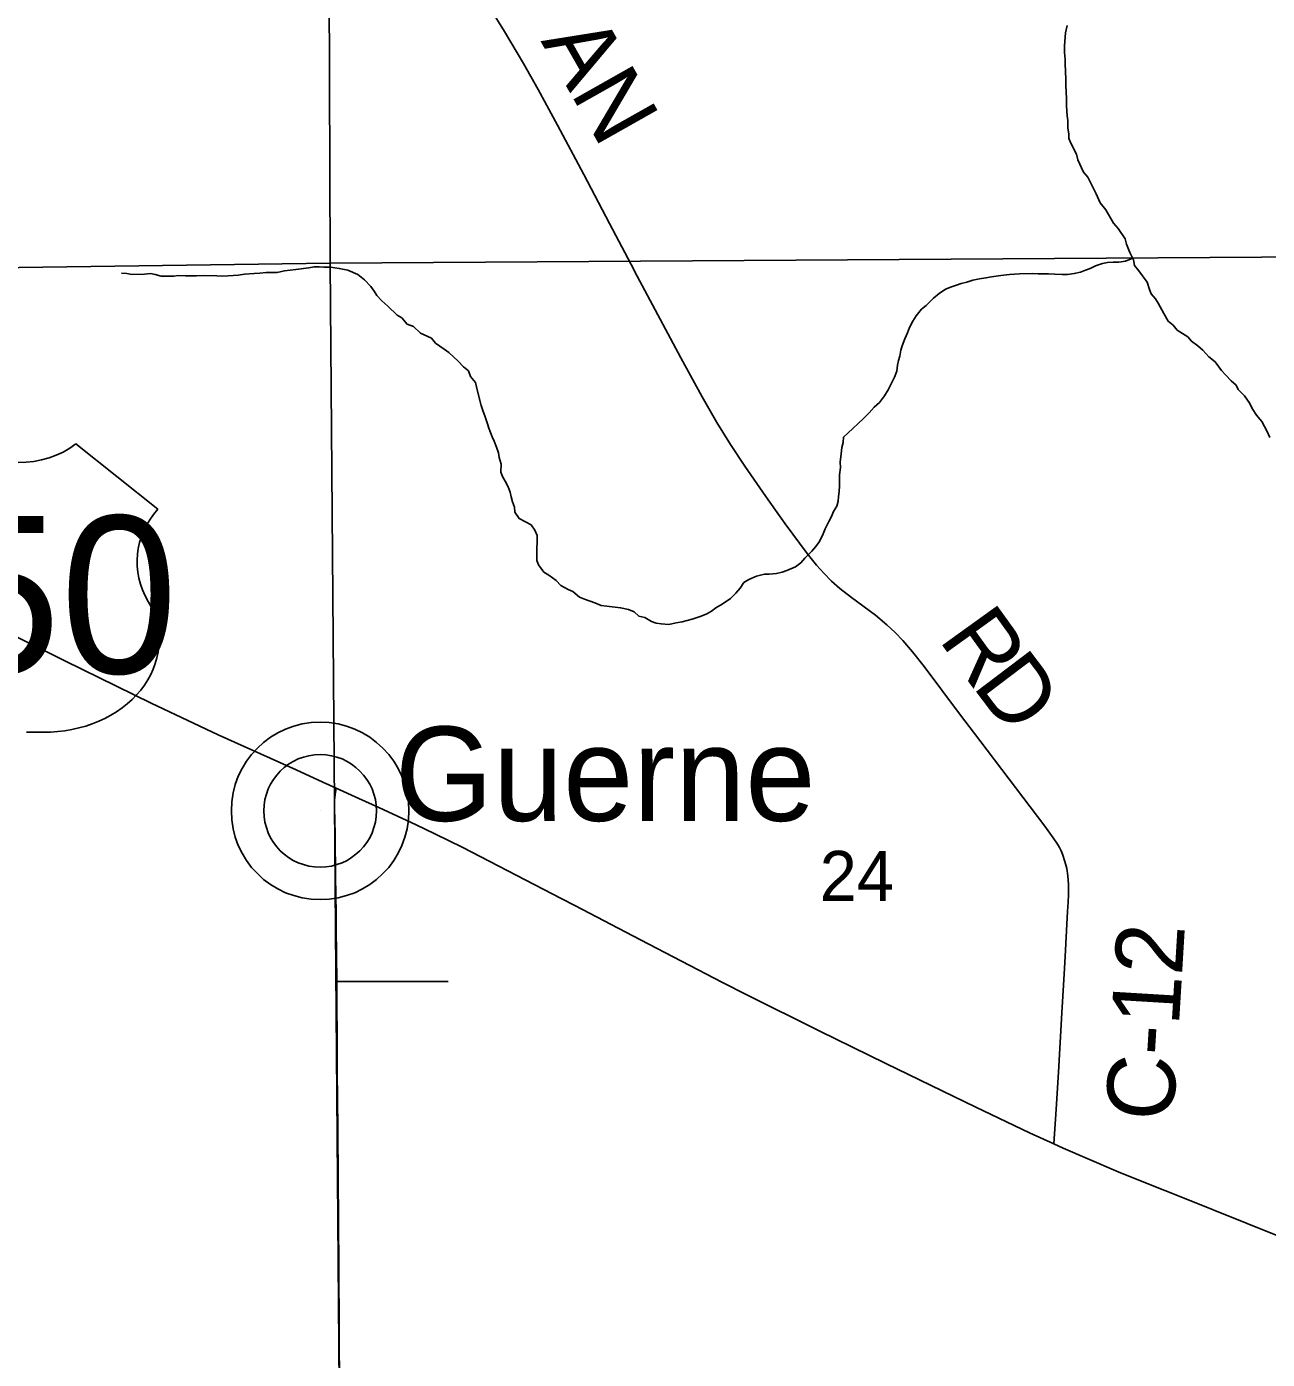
# Model space of a CAD drawing. Extents: x 0 to 34, y 0 to 22.
# Drawn here: x 22.047 to 23.087, y 10.698 to 11.815 of the extents above; entities that cross this region are included whole.
import ezdxf

# ---------------------------------------------------------------- set-up
doc = ezdxf.new("R2010")
doc.units = 0
for name, color, linetype in [('GM_X_County_Road', 7, 'Continuous'), ('GM_X_County_Road_Text', 7, 'Continuous'), ('GM_X_Minor_River', 7, 'Continuous'), ('GM_X_Section', 7, 'Continuous'), ('GM_X_Section_Text', 7, 'Continuous'), ('GM_X_Township_Road', 7, 'Continuous'), ('GM_X_Unincorporated', 7, 'Continuous'), ('GM_X_Unincorporated_Location', 7, 'Continuous'), ('GM_X_Unincorporated_Text', 7, 'Continuous'), ('GM_X_US_Route', 7, 'Continuous'), ('GM_X_US_Shield', 7, 'Continuous')]:
    doc.layers.add(name, color=color, linetype=linetype)

msp = doc.modelspace()

# ---------------------------------------------------------------- linework, layer by layer
at = {"layer": 'GM_X_County_Road'}
for points in [[(22.5536, 11.616), (22.5355, 11.6502), (22.5139, 11.6915), (22.4919, 11.7326), (22.4757, 11.7627), (22.4634, 11.7843), (22.4475, 11.8111), (22.436, 11.8296), (22.4072, 11.8738), (22.3935, 11.8946), (22.3817, 11.9128), (22.3681, 11.9336), (22.3424, 11.9725), (22.3219, 12.0037), (22.2805, 12.0694), (22.2709, 12.0853), (22.2634, 12.0989), (22.2591, 12.1073), (22.2553, 12.1152)], [(22.9077, 10.879), (22.908, 10.8833), (22.9096, 10.9082), (22.9116, 10.9392), (22.9145, 10.9889), (22.9166, 11.026), (22.9175, 11.0414), (22.9187, 11.0631), (22.9193, 11.0739), (22.9197, 11.0815), (22.9201, 11.0876), (22.9201, 11.0963), (22.9196, 11.1036), (22.9186, 11.1097), (22.9171, 11.1158), (22.9151, 11.1218), (22.9139, 11.1247), (22.9124, 11.1275), (22.9108, 11.1302), (22.9073, 11.1354), (22.9001, 11.1454), (22.8457, 11.2171), (22.8286, 11.2393), (22.799, 11.2792), (22.7894, 11.2915), (22.7812, 11.3009), (22.7748, 11.3076), (22.7679, 11.314), (22.7583, 11.322), (22.7383, 11.3368), (22.7286, 11.3445), (22.7216, 11.3506), (22.7151, 11.3572), (22.7089, 11.3641), (22.7012, 11.3737), (22.6827, 11.3987), (22.6664, 11.4214), (22.6488, 11.447), (22.6369, 11.4651), (22.6255, 11.4836), (22.6131, 11.5051), (22.5952, 11.5377), (22.5587, 11.6063), (22.5536, 11.616)], [(22.307, 11.0152), (22.3065, 11.0596), (22.3064, 11.072), (22.306, 11.1032), (22.3056, 11.1364), (22.3053, 11.1519), (22.3051, 11.1585), (22.3051, 11.1626), (22.3051, 11.1658), (22.3052, 11.1674), (22.3054, 11.1692), (22.3057, 11.1717), (22.3066, 11.1772)], [(22.309, 10.7237), (22.3087, 10.7757), (22.3081, 10.8517), (22.3078, 10.889), (22.3075, 10.9199), (22.3074, 10.9366), (22.3073, 10.9422), (22.3073, 10.9723), (22.3072, 10.9921), (22.3071, 11.0073), (22.307, 11.0152)], [(22.3099, 10.1048), (22.3098, 10.173), (22.3098, 10.288), (22.3097, 10.4807), (22.3099, 10.5801), (22.3096, 10.6485), (22.3091, 10.7138), (22.309, 10.7237)]]:
    msp.add_lwpolyline(points, dxfattribs=at)
at = {"layer": 'GM_X_Minor_River'}
for points in [[(22.9185, 11.7488), (22.9185, 11.7549), (22.9179, 11.7663), (22.9179, 11.7712), (22.9173, 11.7841), (22.9173, 11.7879), (22.9168, 11.7936), (22.9167, 11.7993), (22.9174, 11.81), (22.9188, 11.8161)], [(23.0887, 11.4711), (23.0864, 11.476), (23.0821, 11.4843), (23.0775, 11.4896), (23.074, 11.4953), (23.072, 11.4994), (23.0674, 11.5058), (23.0623, 11.5111), (23.0604, 11.5148), (23.0562, 11.5186), (23.0519, 11.5231), (23.0481, 11.5272), (23.043, 11.5343), (23.0376, 11.5385), (23.0326, 11.5441), (23.0284, 11.5478), (23.023, 11.5516), (23.0199, 11.5553), (23.0111, 11.5609), (23.0076, 11.565), (23.0034, 11.5684), (22.9999, 11.5748), (22.9952, 11.5835), (22.9929, 11.5872), (22.9894, 11.5914), (22.9879, 11.5951), (22.9859, 11.6012), (22.9789, 11.6106), (22.9754, 11.6151), (22.9746, 11.62), (22.9715, 11.6261), (22.9687, 11.6329), (22.9675, 11.6374), (22.9617, 11.6461), (22.9578, 11.6506), (22.9512, 11.6619), (22.9466, 11.6675), (22.9431, 11.6751), (22.9361, 11.689), (22.9326, 11.6932), (22.9279, 11.7037), (22.9267, 11.7083), (22.9224, 11.717), (22.9204, 11.7215), (22.9204, 11.7253), (22.9195, 11.7306), (22.9195, 11.7367), (22.919, 11.7405), (22.9185, 11.7488)], [(22.9739, 11.6214), (22.9678, 11.6188), (22.9621, 11.618), (22.9575, 11.6179), (22.9526, 11.6175), (22.9484, 11.6167), (22.9427, 11.6147), (22.9382, 11.6127), (22.9344, 11.6111), (22.9302, 11.6096), (22.9249, 11.6084), (22.9192, 11.6075), (22.9147, 11.6075), (22.9086, 11.6078), (22.9033, 11.6081), (22.8991, 11.608), (22.8945, 11.608), (22.8899, 11.6083), (22.8789, 11.6081), (22.8706, 11.6076), (22.8633, 11.6068), (22.8554, 11.6055), (22.8508, 11.6047), (22.8455, 11.6039), (22.8398, 11.6027), (22.8349, 11.6011), (22.83, 11.5999), (22.8262, 11.5987), (22.822, 11.5971), (22.8171, 11.5952), (22.8118, 11.5917), (22.8069, 11.5878), (22.8009, 11.5816), (22.7968, 11.5785), (22.7923, 11.5728), (22.7897, 11.5686), (22.7867, 11.5632), (22.7852, 11.5586), (22.783, 11.5537), (22.7808, 11.5479), (22.7797, 11.5441), (22.7786, 11.5392), (22.7775, 11.5354), (22.7768, 11.5316), (22.7761, 11.5266), (22.7743, 11.5216), (22.7691, 11.5109), (22.7658, 11.506), (22.7617, 11.5002), (22.7571, 11.4963), (22.753, 11.4917), (22.7481, 11.4867), (22.744, 11.4829), (22.7395, 11.4786), (22.7354, 11.4748), (22.7316, 11.4713), (22.7313, 11.4668), (22.7302, 11.4626), (22.7295, 11.4572), (22.7288, 11.4504), (22.7289, 11.4458), (22.7282, 11.4397), (22.7283, 11.4306), (22.728, 11.4257), (22.7273, 11.4215), (22.727, 11.4177), (22.7259, 11.4135), (22.7233, 11.4089), (22.7214, 11.4047), (22.7192, 11.4005), (22.7162, 11.3944), (22.7144, 11.3902), (22.7114, 11.3837), (22.7085, 11.3795), (22.7051, 11.3756), (22.6991, 11.3698), (22.6957, 11.366), (22.6912, 11.3625), (22.684, 11.3594), (22.6802, 11.3582), (22.6753, 11.357), (22.6692, 11.3565), (22.6654, 11.3565), (22.6586, 11.3549), (22.6521, 11.3521), (22.648, 11.3494), (22.645, 11.3448), (22.6413, 11.3406), (22.6368, 11.336), (22.63, 11.3313), (22.6247, 11.3282), (22.6209, 11.3255), (22.6171, 11.3232), (22.6122, 11.3212), (22.6047, 11.3188), (22.5963, 11.3164), (22.5914, 11.3156), (22.5853, 11.3144), (22.5788, 11.3147), (22.5747, 11.3154), (22.5708, 11.3169)], [(22.5708, 11.3169), (22.5651, 11.3202), (22.5601, 11.3213), (22.5563, 11.325), (22.5513, 11.3268), (22.5448, 11.3283), (22.5334, 11.3296), (22.5284, 11.3303), (22.5231, 11.3325), (22.5147, 11.3355), (22.5105, 11.3373), (22.5047, 11.3418), (22.5009, 11.3436), (22.4948, 11.347), (22.4909, 11.3511), (22.4848, 11.3556), (22.4805, 11.3582), (22.4759, 11.3642), (22.4747, 11.368), (22.4746, 11.3786), (22.4749, 11.3828), (22.4748, 11.3889), (22.4729, 11.3934), (22.4698, 11.3979), (22.4652, 11.4002), (22.4598, 11.4031), (22.4563, 11.4084), (22.4559, 11.4126), (22.4543, 11.4171), (22.4531, 11.4213), (22.4523, 11.4251), (22.4507, 11.4296), (22.448, 11.4345), (22.446, 11.4383), (22.4445, 11.442), (22.4448, 11.4485), (22.4432, 11.4542), (22.4424, 11.458), (22.4408, 11.4629), (22.4388, 11.4678), (22.4372, 11.4716), (22.4345, 11.4788), (22.4333, 11.4825), (22.4313, 11.4882), (22.4293, 11.4935), (22.4281, 11.4977), (22.4249, 11.5098), (22.4233, 11.517), (22.4191, 11.5222), (22.4175, 11.5268), (22.4133, 11.5301), (22.4086, 11.535), (22.4009, 11.5421), (22.3971, 11.5451), (22.3898, 11.55), (22.3863, 11.5541), (22.3772, 11.5585), (22.3714, 11.5641), (22.366, 11.566), (22.3614, 11.5712), (22.3576, 11.5735), (22.3499, 11.5809), (22.3449, 11.5854), (22.3406, 11.5899), (22.3383, 11.5937), (22.3356, 11.5975), (22.3302, 11.6031), (22.3248, 11.6076), (22.3164, 11.6113), (22.3091, 11.6127), (22.3019, 11.6137), (22.2962, 11.6137), (22.2924, 11.614), (22.2882, 11.6139), (22.2836, 11.6131), (22.2726, 11.6118), (22.2631, 11.6106), (22.2571, 11.6093), (22.2479, 11.6092), (22.2426, 11.6088), (22.2377, 11.6083), (22.2297, 11.6078), (22.2244, 11.607), (22.216, 11.6065), (22.2115, 11.6061), (22.2065, 11.6064), (22.1955, 11.6066), (22.1894, 11.6065), (22.1856, 11.6065), (22.1803, 11.6064), (22.1742, 11.6067), (22.1704, 11.6063), (22.1598, 11.6061), (22.1548, 11.6076), (22.151, 11.6083), (22.146, 11.6079), (22.1354, 11.6077), (22.1312, 11.6084), (22.1266, 11.6087)]]:
    msp.add_lwpolyline(points, dxfattribs=at)
at = {"layer": 'GM_X_Section'}
for points in [[(23.2871, 12.632), (23.2872, 12.6207), (23.2983, 11.6235), (22.3015, 11.617), (22.2979, 12.6206)], [(21.3125, 12.6129), (22.2979, 12.6206), (22.3015, 11.617), (21.2987, 11.6032), (21.3118, 11.9349)], [(22.3015, 11.617), (22.3097, 10.6062), (21.3072, 10.5992), (21.2987, 11.6032)], [(23.2983, 11.6235), (23.3079, 10.6196), (22.3097, 10.6062), (22.3015, 11.617)]]:
    msp.add_lwpolyline(points, close=True, dxfattribs=at)
at = {"layer": 'GM_X_Township_Road'}
msp.add_lwpolyline([(22.307, 11.0152), (22.3393, 11.015), (22.3631, 11.015), (22.3941, 11.0152), (22.4004, 11.0152)], dxfattribs=at)
at = {"layer": 'GM_X_Unincorporated'}
for radius in [0.0744, 0.0472]:
    msp.add_circle((22.2931, 11.1581), radius, dxfattribs=at)
at = {"layer": 'GM_X_Unincorporated_Location'}
msp.add_line((22.2931, 11.1581), (22.2931, 11.1581), dxfattribs=at)
at = {"layer": 'GM_X_US_Route'}
for points in [[(22.0206, 11.3128), (22.0791, 11.2839), (22.1515, 11.2483), (22.2077, 11.2218), (22.273, 11.1926), (22.2954, 11.1822), (22.3066, 11.1772), (22.3254, 11.1685), (22.3424, 11.1609), (22.3735, 11.1465), (22.3891, 11.1389), (22.4125, 11.1273), (22.495, 11.0848)], [(22.495, 11.0848), (22.5065, 11.0789), (22.5616, 11.0499), (22.6302, 11.0143)], [(22.6302, 11.0143), (22.6499, 11.0041), (22.7111, 10.9737), (22.767, 10.9465), (22.8425, 10.9097), (22.8873, 10.8883), (22.9077, 10.879), (22.9156, 10.8754), (22.9356, 10.8667), (22.9617, 10.8557), (22.9873, 10.8454), (23.0142, 10.8346), (23.0969, 10.8014), (23.1605, 10.7761), (23.1839, 10.7677), (23.1926, 10.7649), (23.2017, 10.7625), (23.2095, 10.7607), (23.2167, 10.7592), (23.2277, 10.7573), (23.2382, 10.7558), (23.2814, 10.751), (23.3062, 10.7482), (23.3082, 10.748)]]:
    msp.add_lwpolyline(points, dxfattribs=at)
at = {"layer": 'GM_X_US_Shield'}
for p, q in [((22.1571, 11.4108), (22.0884, 11.4657)), ((22.0472, 11.224), (22.061, 11.224))]:
    msp.add_line(p, q, dxfattribs=at)
for centre, major_axis, start_param, end_param in [((22.0404, 11.5049), (-0.0687, 0), 0.795399, 2.346194), ((22.2358, 11.3667), (-0.0961, 0), 5.672304, 6.727422), ((22.062, 11.3009), (-0.0961, 0), 1.559657, 3.580859)]:
    msp.add_ellipse(centre, major_axis=major_axis, ratio=0.8, start_param=start_param, end_param=end_param, dxfattribs=at)

# ---------------------------------------------------------------- texts
at = {"layer": 'GM_X_County_Road_Text'}
for s, height, rotation, p in [('A', 0.0568, 299.6789, (22.4776, 11.8032)), ('N', 0.0568, 299.4661, (22.5023, 11.7598)), ('R', 0.0568, 305.7559, (22.8106, 11.3019)), ('D', 0.0568, 307.1527, (22.8388, 11.2629)), ('C-12', 0.05682, 86.5529, (23.0077, 10.8973))]:
    msp.add_text(s, height=height, rotation=rotation, dxfattribs=at).set_placement(p)
at = {"layer": 'GM_X_Section_Text'}
msp.add_text('24', height=0.04186, rotation=0, dxfattribs=at).set_placement((22.7116, 11.0827))
at = {"layer": 'GM_X_Unincorporated_Text'}
msp.add_text('Guerne', height=0.07898, rotation=0, dxfattribs=at).set_placement((22.3558, 11.1497))
at = {"layer": 'GM_X_US_Shield'}
msp.add_text('250', height=0.13184, dxfattribs=at).set_placement((21.8795, 11.2734))

doc.saveas('drawing.dxf')
